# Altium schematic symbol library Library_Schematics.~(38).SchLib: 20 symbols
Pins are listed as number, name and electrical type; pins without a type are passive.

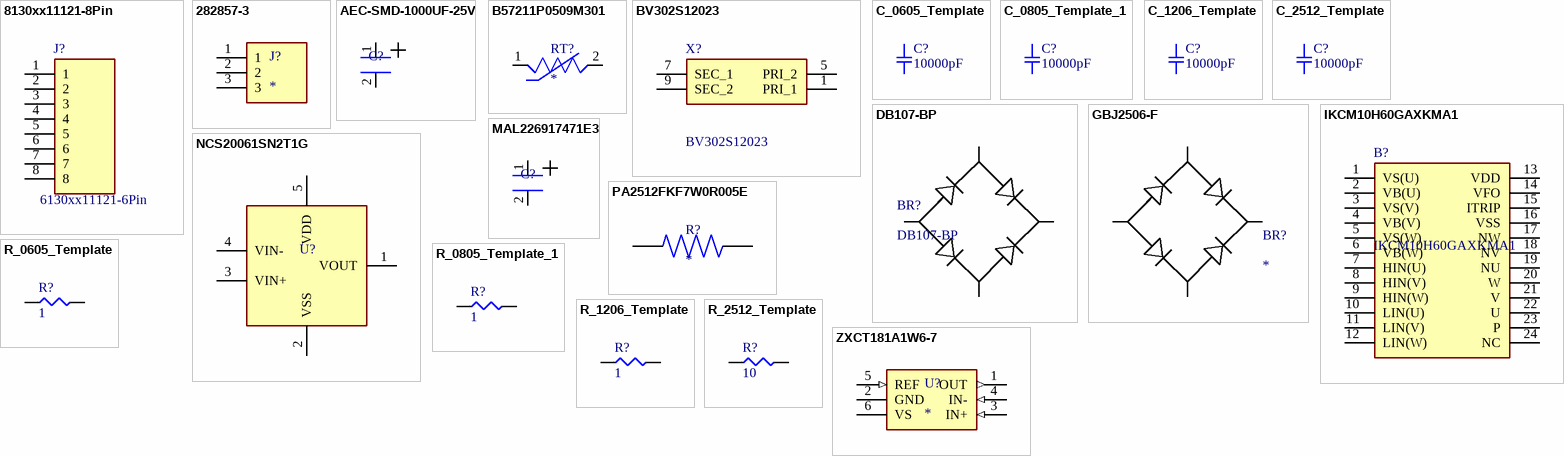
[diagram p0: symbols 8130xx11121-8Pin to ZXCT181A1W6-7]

## 8130xx11121-8Pin
designator J?, comment 6130xx11121-6Pin
2.54MM PIN HEADER; Manufacturer_Name: Wurth Elektronik; Geometry.Height: 8.69mm
footprint 200_HDRV6W64P0X254_1X6_1524X254X869P
pins: 1, 2, 3, 4, 5, 6, 7, 8

## 282857-3
designator J?
3 Position Wire to Board Terminal Block Horizontal with Board 0.200 (5.08mm) Through Hole; MF: TE Connectivity; MP: 282857-3
footprint 201_TE_282857-3
pins: 1, 2, 3

## AEC-SMD-1000UF-25V
designator C?
1000 µF, 25 V polarized aluminum electrolytic capacitor, SMD V-chip package, Ø10 mm body, approx. 10.5 mm height, 105 °C rated.
footprint 098_AEC-SMD-1000UF-25V
pins: 1, 2

## B57211P0509M301
designator RT?
Inrush Current Limiter 5 Ohms Â±20% 5 A 0.512 (13.00mm); MF: EPCOS; MP: B57211P0509M301
footprint 307_THRMRB750W80L1300T600H2000
pins: 1, 2

## BV302S12023
designator X?
2.3VA Encapsulated Transformer 50/60Hz; Manufacturer_Name: Zettler Group; Geometry.Height: 29.8mm
footprint 899_BV302S12023
pins: 1 PRI_1, 5 PRI_2, 7 SEC_1, 9 SEC_2

## C_0605_Template
designator C?, comment 10000pF
CAP CER 0605; Part Number: GC321AD72E103KX01D; Manufacturer: Murata Electronics North America; Factory Stock: 0; Unit Price (USD): 0.3; Minimum Quantity: 1; Tolerance: ±10%; Voltage: 250V; Temperature Coefficient: X7T
footprint 006_SMD_0605
pins: 1, 2

## C_0805_Template_1
designator C?, comment 10000pF
CAP CER 0805; Part Number: GC321AD72E103KX01D; Manufacturer: Murata Electronics North America; Factory Stock: 0; Unit Price (USD): 0.3; Minimum Quantity: 1; Tolerance: ±10%; Voltage: 250V; Temperature Coefficient: X7T
footprint 000_SMD-0805
pins: 1, 2

## C_1206_Template
designator C?, comment 10000pF
CAP CER 1206; Part Number: GC321AD72E103KX01D; Manufacturer: Murata Electronics North America; Factory Stock: 0; Unit Price (USD): 0.3; Minimum Quantity: 1; Tolerance: ±10%; Voltage: 250V; Temperature Coefficient: X7T
footprint 001_SMD-1206
pins: 1, 2

## C_2512_Template
designator C?, comment 10000pF
CAP CER 2512; Part Number: GC321AD72E103KX01D; Manufacturer: Murata Electronics North America; Factory Stock: 0; Unit Price (USD): 0.3; Minimum Quantity: 1; Tolerance: ±10%; Voltage: 250V; Temperature Coefficient: X7T
footprint 002_SMD-2512
pins: 1, 2

## DB107-BP
designator BR?
Description; Manufacturer_Name: MCC
footprint 898_DB107-BP
pins: 1, 2, 3, 4

## GBJ2506-F
designator BR?
Bridge Rectifier; Manufacturer_Name: Diodes Incorporated; Manufacturer_Part_Number: GBJ2506-F
footprint 996_GBJ_1
pins: 1, 2, 3, 4

## IKCM10H60GAXKMA1
designator B?
Intelligent Power Module 3-Ph 600V 10A; Manufacturer_Name: Infineon; Geometry.Height: 5.6mm
footprint 997_IKCM10H60GAXKMA1
pins: 1 VS(U), 2 VB(U), 3 VS(V), 4 VB(V), 5 VS(W), 6 VB(W), 7 HIN(U), 8 HIN(V), 9 HIN(W), 10 LIN(U), 11 LIN(V), 12 LIN(W), 13 VDD, 14 VFO, 15 ITRIP, 16 VSS, 17 NW, 18 NV, 19 NU, 20 W, 21 V, 22 U, 23 P, 24 NC

## MAL226917471E3
designator C?
470 µF, 450 V polarized aluminum electrolytic capacitor, snap-in THT, Ø35 mm body, 10 mm lead spacing, 105 °C rated.
footprint 099_MAL226917471E3
pins: 1, 2

## NCS20061SN2T1G
designator U?
Single, rail-to-rail operational amplifier used as a voltage buffer for the 1.65 V current-sense reference.
footprint 897_NCS20061SN2T1G
pins: 1 VOUT, 2 VSS, 3 VIN+, 4 VIN-, 5 VDD

## PA2512FKF7W0R005E
designator R?
5 mΩ, 2 W, ±1% current-sense shunt resistor, 2512 (6332 metric) SMD package, low-resistance metal-element construction.; MF: Bourns; MP: CRF2512-FZ-R005ELF
footprint 097_PA2512FKF7W0R005E (5 mΩ, 2 W, ±1% current-sense shunt resistor, 2512 (6332 metric) SMD package, low-resistance metal-element construction.)
pins: 1, 2

## R_0605_Template
designator R?, comment 1
RES SMD 0605; Part Number: ERJ-6BQF1R0V; Manufacturer: Panasonic Electronic Components; Factory Stock: 0; Unit Price (USD): 0.05834; @ qty: 1500; Tolerance: ±1%; Power (Watts): 0.333W, 1/3W; Temperature Coefficient: ±200ppm/°C
footprint 006_SMD_0605
pins: 1, 2

## R_0805_Template_1
designator R?, comment 1
RES SMD 0805; Part Number: ERJ-6BQF1R0V; Manufacturer: Panasonic Electronic Components; Factory Stock: 0; Unit Price (USD): 0.05834; @ qty: 1500; Tolerance: ±1%; Power (Watts): 0.333W, 1/3W; Temperature Coefficient: ±200ppm/°C
footprint 000_SMD-0805
pins: 1, 2

## R_1206_Template
designator R?, comment 1
RES SMD 1206; Part Number: ERJ-8BQF1R0V; Manufacturer: Panasonic Electronic Components; Factory Stock: 0; Unit Price (USD): 0.05778; @ qty: 1500; Tolerance: ±1%; Power (Watts): 0.5W, 1/2W; Temperature Coefficient: ±200ppm/°C
footprint 001_SMD-1206
pins: 1, 2

## R_2512_Template
designator R?, comment 10
RES SMD 2512; Part Number: ERJ-1TNF10R0U; Manufacturer: Panasonic Electronic Components; Factory Stock: 0; Unit Price (USD): 0.14799; @ qty: 1500; Minimum Quantity: 1; Tolerance: ±1%; Power (Watts): 1W; Temperature Coefficient: ±100ppm/°C
footprint 002_SMD-2512
pins: 1, 2

## ZXCT181A1W6-7
designator U?
Bidirectional high-side current-sense amplifier, fixed gain 20 V/V, 2.7–5.5 V supply, up to 26 V common-mode input range, SOT-26 package.; MF: Texas Instruments; MP: INA181A1IDBVR
footprint 896_ZXCT181A1W6-7
pins: 1 OUT (out), 2 GND (power), 3 IN+ (in), 4 IN- (in), 5 REF (in), 6 VS (power)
